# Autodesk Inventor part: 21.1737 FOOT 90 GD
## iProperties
Created: 2007-04
Part Number: 21.1737 FOOT 90 GD
Document SubType Name: Modeling
Designer: Andy Moles
Material: Aluminum-6061
Density: 2.71 g/cm^3
Author: Andy Moles
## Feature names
1. Extrusion1
2. Extrusion2
3. Extrusion3
4. Extrusion4
5. Fillet1
6. Fillet2
7. Fillet5
8. Extrusion8
9. Extrusion9
10. Mirror3
11. Fillet7
12. Fillet8
